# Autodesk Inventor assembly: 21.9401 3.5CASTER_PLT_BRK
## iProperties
Created: 2010-10
Part Number: 21.9401 3.5CASTER_PLT_BRK
Document SubType Name: Assembly
Designer: Administrator
Translation Standard: STEP AP214IS
FileName: Colson-2.03256.445 BRK5 .step.step
PreProcessor: SolidWorks 2010
PostProcessor: Build: 236a, Release: 2009 RTM - Date: Fri 02/22/2008
Sent Units: Inches
Uncertainty: 1e-05
Author: Administrator
